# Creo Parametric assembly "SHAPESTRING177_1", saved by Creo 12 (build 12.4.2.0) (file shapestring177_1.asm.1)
Units: Custom; MM, KILOGRAM, SECS

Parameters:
  PTC_WM_ITERATION = "0"
  PTC_WM_VERSION = "-.0"
  PTC_WM_LIFECYCLE_STATE = "In Work"
  PTC_WM_LIFECYCLE = "MO_CADDocument"
  PTC_WM_CREATED_BY = "Maximilian Roepper (Z0017RMS: MO)"
  PTC_WM_CREATED_ON = "18-Sep-26 11:36:42 AM"
  PTC_WM_MODIFIED_BY = "Maximilian Roepper (Z0017RMS: MO)"
  PTC_WM_MODIFIED_ON = "18-Sep-26 11:36:46 AM"
  PDMLINKNUMBER = "PDM000071454780"
  PTC_WM_NUMBER = "PDM000071454780"

Other parameters: WEIGHT, WEIGHT_FACTOR, WEIGHT_ADD, MC_ERRORS, SUPPLIER

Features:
  1. coordinate system
  2. imported feature
  3. component "SHAPESTRING082_1"
  4. component "SHAPESTRING172_1"
  5. component "SHAPESTRING173_1"
  6. component "SHAPESTRING174_1"
  7. component "SHAPESTRING175_1"
  8. component "SHAPESTRING176_1"

Other named items: DRW_VIEW_ORG, ROUGH-GROB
